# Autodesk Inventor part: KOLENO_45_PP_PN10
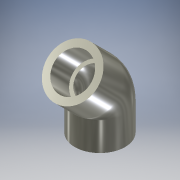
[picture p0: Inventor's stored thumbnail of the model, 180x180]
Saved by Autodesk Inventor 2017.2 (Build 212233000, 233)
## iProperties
Created: 2016-11
Part Number: KOLENO_45_PP_PN10
Material: Polypropylen
Document SubType Name: Modeling
Designer: CADstudio
Mass: 11.621 g
Surface Area: 68.0673 cm^2
Volume: 12.9266 cm^3
Density: 0.899 g/cm^3
Appearance: Hladká – popel
Vendor: KOWA
Categories: <MemberInstance><Categories><Category DisplayName="" InternalName="4347fa0f-2144-441d-94cd-e3e15c92b736" Mnemonic="TUBEANDPIPE"><CategoryParameter DisplayName="
Mass: 0,012
Author: CADstudio
Title: KOLENO PP PN10
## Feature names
1. Tažení1
2. Vysunutí1 [Extrusion]
3. Vysunutí2 [Extrusion]
## Parameters: EXTERNI = 27.5 mm, VNI = 16.2 mm, H_OSA = 27.5 mm, d5 = 0, d6 = 0, Z_OSA = 6.5 mm, d8 = 14.5 mm, d9 = 0, d11 = 14.5 mm, d12 = 0, d13 = 45 deg, H_OBLOUK = 21 mm, d15 = 13.75 mm
